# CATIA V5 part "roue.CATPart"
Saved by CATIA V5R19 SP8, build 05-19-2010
Part number: roue
Revision: ANY
Definition: UNKNOWN
Nomenclature: 16
Source: Unknown
Bounding box of the stored display mesh (mm): x -20.231 to 20.231, y -20.231 to 20.231, z -1 to 7.5
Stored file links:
  D:\Documents\1_Travail\2- 2I2D\1 - Cours et TD\2- TD\3-TD Assemblage\Pompe AirMan\roue.CATPart
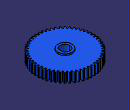
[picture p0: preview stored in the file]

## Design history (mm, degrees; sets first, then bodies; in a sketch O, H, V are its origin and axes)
Body1 "Répétition circulaire1" (main body)
  Solid1: solid without history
